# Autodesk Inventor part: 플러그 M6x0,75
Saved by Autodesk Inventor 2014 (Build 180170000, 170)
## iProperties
Created: 2026-04
Part Number: 플러그 M6x0,75
Material: 일반
Document SubType Name: Modeling
Designer: dg
Density: 1 g/cm^3
Appearance: 기본값
Author: dg
Author: jhkim
Description: 6각 머리 볼트 및 6각 머리 나사
Creation Date: 2026-03-26
Sending System: Autodesk Inventor 2026
Preprocessor: ST-DEVELOPER v20.1
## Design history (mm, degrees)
node "플러그 M6x0,751"
body "Solid1"
node "기준1"
